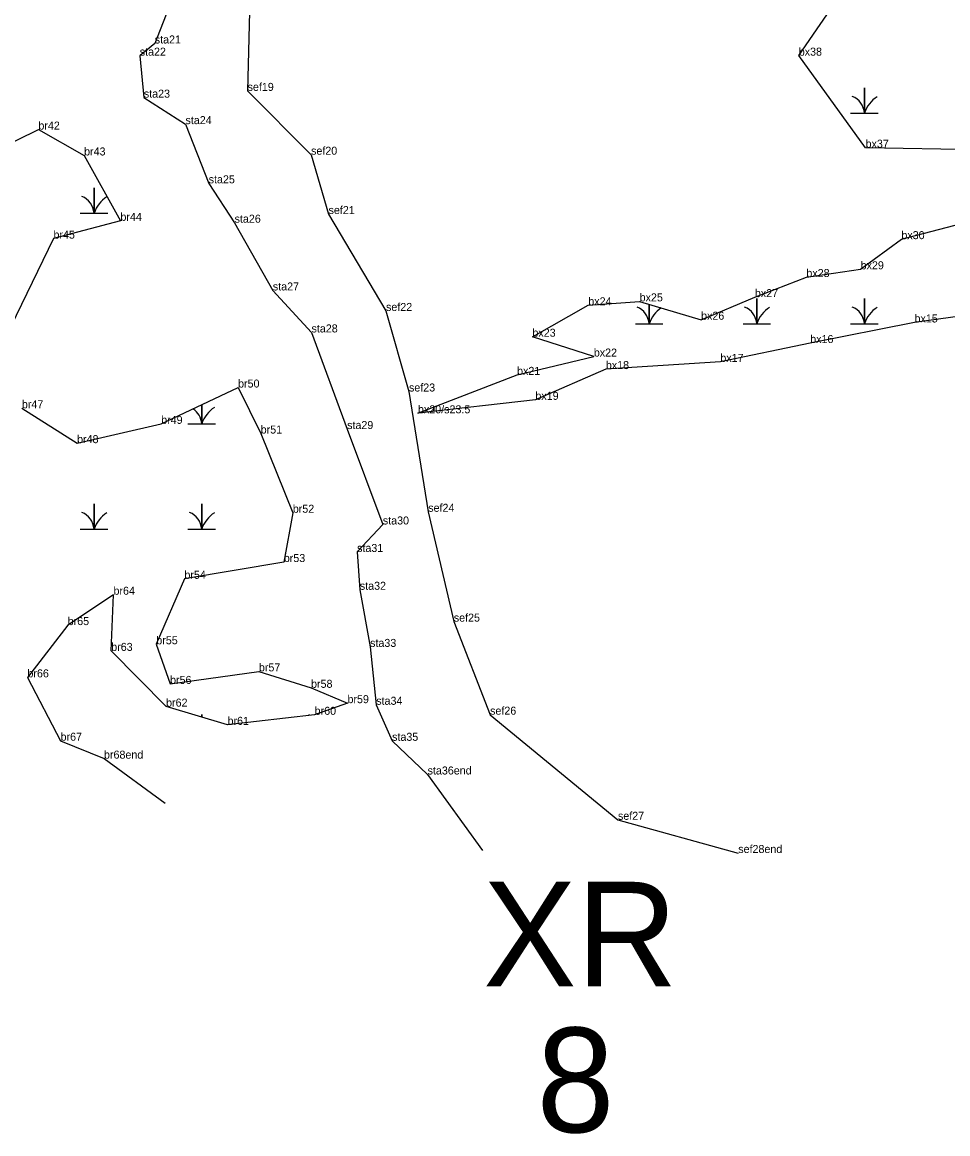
# Model space of a CAD drawing. Extents: x 2072529 to 2268796, y 436423 to 470406.
# Drawn here: x 2233128 to 2233706, y 437609 to 438303 of the extents above; entities that cross this region are included whole.
import ezdxf

# ---------------------------------------------------------------- set-up
doc = ezdxf.new("R2010")
doc.units = 0
for name, color, linetype in [('Default', 7, 'Continuous'), ('Exist Environmental Wetland Boundary Cogo Comment', 7, 'Continuous'), ('Exist Environmental Wetland Boundary Cogo Point CELL', 7, 'Continuous'), ('Exist Hydro Jurisdictional Stream or Body of Water NEU Mitigable Cogo Comment', 7, 'Continuous'), ('Old_Level_20', 7, 'Continuous'), ('Old_Level_52', 7, 'Continuous')]:
    doc.layers.add(name, color=color, linetype=linetype)

msp = doc.modelspace()

# ---------------------------------------------------------------- linework, layer by layer
at = {"layer": 'Exist Environmental Wetland Boundary Cogo Point CELL'}
for points in [[(2233645.48, 438246.13), (2233654.08, 438246.13), (2233654.08, 438261.91), (2233654.08, 438246.13), (2233662.68, 438246.13)], [(2233164.16, 438183.63), (2233172.76, 438183.63), (2233172.76, 438199.41), (2233172.76, 438183.63), (2233181.36, 438183.63)], [(2233510.98, 438114.53), (2233519.58, 438114.53), (2233519.58, 438126.76)], [(2233519.58, 438126.76), (2233519.58, 438114.53), (2233528.18, 438114.53)], [(2233578.23, 438114.53), (2233586.83, 438114.53), (2233586.83, 438130.31), (2233586.83, 438114.53), (2233595.43, 438114.53)], [(2233645.48, 438114.53), (2233654.08, 438114.53), (2233654.08, 438130.31), (2233654.08, 438114.53), (2233662.68, 438114.53)], [(2233231.41, 438052.03), (2233240.01, 438052.03), (2233240.01, 438063.95)], [(2233240.01, 438063.95), (2233240.01, 438052.03), (2233248.61, 438052.03)], [(2233385.08, 438059.74), (2233385.08, 438062.45)], [(2233385.08, 438062.45), (2233385.08, 438059.74)], [(2233164.16, 437986.23), (2233172.76, 437986.23), (2233172.76, 438002.01), (2233172.76, 437986.23), (2233181.36, 437986.23)], [(2233231.41, 437986.23), (2233240.01, 437986.23), (2233240.01, 438002.01), (2233240.01, 437986.23), (2233248.61, 437986.23)], [(2233240.01, 437868.77), (2233240.01, 437870.41), (2233240.01, 437868.77)], [(2233307.26, 437869.86), (2233307.26, 437870.41), (2233307.26, 437869.86)]]:
    msp.add_lwpolyline(points, dxfattribs=at)
for centre, radius, start, end in [((2233641.81, 438245.24), 12.3, 4.14034, 67.53497), ((2233672.32, 438240.07), 19.22, 122.12745, 161.62219), ((2233160.49, 438182.75), 12.3, 4.14034, 67.53497), ((2233191, 438177.57), 19.22, 122.12745, 161.62219), ((2233507.31, 438113.64), 12.3, 4.14034, 67.53497), ((2233537.82, 438108.47), 19.22, 123.57431, 161.62219), ((2233574.56, 438113.64), 12.3, 4.14034, 67.53497), ((2233605.07, 438108.47), 19.22, 122.12745, 161.62219), ((2233641.81, 438113.64), 12.3, 4.14034, 67.53497), ((2233672.32, 438108.47), 19.22, 122.12745, 161.62219), ((2233227.74, 438051.15), 12.3, 4.14034, 56.30829), ((2233258.25, 438045.97), 19.22, 122.12745, 161.62219), ((2233372.81, 438047.84), 12.3, 64.46323, 67.53497), ((2233160.49, 437985.35), 12.3, 4.14034, 67.53497), ((2233191, 437980.17), 19.22, 122.12745, 161.62219), ((2233227.74, 437985.35), 12.3, 4.14034, 67.53497), ((2233258.25, 437980.17), 19.22, 122.12745, 161.62219)]:
    msp.add_arc(centre, radius, start, end, dxfattribs=at)
at = {"layer": 'Old_Level_20'}
for p, q in [((2233210.7, 438289.64), (2233210.7, 438289.64)), ((2233201.3, 438282.01), (2233201.3, 438282.01)), ((2233613.07, 438282.03), (2233613.07, 438282.03)), ((2233268.69, 438260.03), (2233268.69, 438260.03)), ((2233203.87, 438255.8), (2233203.87, 438255.8)), ((2233229.89, 438239.26), (2233229.89, 438239.26)), ((2233137.99, 438235.84), (2233137.99, 438235.84)), ((2233654.83, 438224.52), (2233654.83, 438224.52)), ((2233166.54, 438219.69), (2233166.54, 438219.69)), ((2233308.34, 438220.15), (2233308.34, 438220.15)), ((2233244.38, 438202.27), (2233244.38, 438202.27)), ((2233319.29, 438183.08), (2233319.29, 438183.08)), ((2233189.25, 438178.84), (2233189.25, 438178.84)), ((2233260.58, 438177.67), (2233260.58, 438177.67)), ((2233147.41, 438167.71), (2233147.41, 438167.71)), ((2233677.19, 438167.39), (2233677.19, 438167.39)), ((2233651.73, 438148.58), (2233651.73, 438148.58)), ((2233617.82, 438143.72), (2233617.82, 438143.72)), ((2233284.46, 438135.36), (2233284.46, 438135.36)), ((2233481.56, 438126.08), (2233481.56, 438126.08)), ((2233513.65, 438128.53), (2233513.65, 438128.53)), ((2233585.63, 438131.16), (2233585.63, 438131.16)), ((2233355.17, 438122.55), (2233355.17, 438122.55)), ((2233552.04, 438117.06), (2233552.04, 438117.06)), ((2233685.39, 438115.35), (2233685.39, 438115.35)), ((2233308.64, 438109.12), (2233308.64, 438109.12)), ((2233446.66, 438106.45), (2233446.66, 438106.45)), ((2233620.22, 438102.5), (2233620.22, 438102.5)), ((2233485.02, 438094.05), (2233485.02, 438094.05)), ((2233492.53, 438086.24), (2233492.53, 438086.24)), ((2233564.09, 438090.74), (2233564.09, 438090.74)), ((2233437.07, 438082.61), (2233437.07, 438082.61)), ((2233262.75, 438074.7), (2233262.75, 438074.7)), ((2233369.53, 438072.22), (2233369.53, 438072.22)), ((2233448.52, 438067.02), (2233448.52, 438067.02)), ((2233375.15, 438058.6), (2233375.15, 438058.6)), ((2233214.69, 438051.99), (2233214.69, 438051.99)), ((2233276.88, 438045.98), (2233276.88, 438045.98)), ((2233330.87, 438048.76), (2233330.87, 438048.76)), ((2233162.16, 438039.96), (2233162.16, 438039.96)), ((2233296.94, 437996.49), (2233296.94, 437996.49)), ((2233381.56, 437997.08), (2233381.56, 437997.08)), ((2233353.19, 437989.16), (2233353.19, 437989.16)), ((2233337.09, 437971.98), (2233337.09, 437971.98)), ((2233291.32, 437965.69), (2233291.32, 437965.69)), ((2233229.22, 437955.21), (2233229.22, 437955.21)), ((2233184.9, 437945.25), (2233184.9, 437945.25)), ((2233338.81, 437948.36), (2233338.81, 437948.36)), ((2233156.28, 437926.3), (2233156.28, 437926.3)), ((2233397.53, 437928.46), (2233397.53, 437928.46)), ((2233211.66, 437914.32), (2233211.66, 437914.32)), ((2233345.22, 437912.66), (2233345.22, 437912.66)), ((2233183.48, 437910.18), (2233183.48, 437910.18)), ((2233275.76, 437897.37), (2233275.76, 437897.37)), ((2233131.14, 437893.65), (2233131.14, 437893.65)), ((2233220.26, 437889.55), (2233220.26, 437889.55)), ((2233308.35, 437887.12), (2233308.35, 437887.12)), ((2233331.11, 437877.52), (2233331.11, 437877.52)), ((2233349.07, 437876.52), (2233349.07, 437876.52)), ((2233217.77, 437875.37), (2233217.77, 437875.37)), ((2233310.59, 437870.25), (2233310.59, 437870.25)), ((2233420.19, 437870.33), (2233420.19, 437870.33)), ((2233256.17, 437863.98), (2233256.17, 437863.98)), ((2233151.85, 437854.06), (2233151.85, 437854.06)), ((2233358.97, 437854.01), (2233358.97, 437854.01)), ((2233178.98, 437842.87), (2233178.98, 437842.87)), ((2233381.16, 437832.97), (2233381.16, 437832.97)), ((2233500.1, 437804.66), (2233500.1, 437804.66)), ((2233575.26, 437783.92), (2233575.26, 437783.92))]:
    msp.add_line(p, q, dxfattribs=at)
for points in [[(2233725.42, 438223.22), (2233654.83, 438224.52), (2233613.07, 438282.03), (2233650.73, 438337.13)], [(2233085.81, 438210.21), (2233137.99, 438235.84), (2233166.54, 438219.69), (2233189.25, 438178.84), (2233147.41, 438167.71), (2233113.9, 438099.14)], [(2233736.36, 438122.5), (2233685.39, 438115.35), (2233620.22, 438102.5), (2233564.09, 438090.74), (2233492.53, 438086.24), (2233448.52, 438067.02), (2233375.15, 438058.6), (2233437.07, 438082.61), (2233485.02, 438094.05), (2233446.66, 438106.45), (2233481.56, 438126.08), (2233513.65, 438128.53), (2233552.04, 438117.06), (2233585.63, 438131.16), (2233617.82, 438143.72), (2233651.73, 438148.58), (2233677.19, 438167.39), (2233757.1, 438188.17)], [(2233127.67, 438061.76), (2233162.16, 438039.96), (2233214.69, 438051.99), (2233262.75, 438074.7), (2233276.88, 438045.98), (2233296.94, 437996.49), (2233291.32, 437965.69), (2233229.22, 437955.21), (2233211.66, 437914.32), (2233220.26, 437889.55), (2233275.76, 437897.37), (2233308.35, 437887.12), (2233331.11, 437877.52), (2233310.59, 437870.25), (2233256.17, 437863.98), (2233217.77, 437875.37), (2233183.48, 437910.18), (2233184.9, 437945.25), (2233156.28, 437926.3), (2233131.14, 437893.65), (2233151.85, 437854.06), (2233178.98, 437842.87), (2233217.26, 437814.97)]]:
    msp.add_lwpolyline(points, dxfattribs=at)
at = {"layer": 'Old_Level_52'}
for points in [[(2233270.05, 438317.86), (2233268.69, 438260.03), (2233308.34, 438220.15), (2233319.29, 438183.08), (2233355.17, 438122.55), (2233369.53, 438072.22), (2233381.56, 437997.08), (2233397.53, 437928.46), (2233420.19, 437870.33), (2233500.1, 437804.66), (2233575.26, 437783.92)], [(2233219.22, 438311.43), (2233210.7, 438289.64), (2233201.3, 438282.01), (2233203.87, 438255.8), (2233229.89, 438239.26), (2233244.38, 438202.27), (2233260.58, 438177.67), (2233284.46, 438135.36), (2233308.64, 438109.12), (2233330.87, 438048.76), (2233353.19, 437989.16), (2233337.09, 437971.98), (2233338.81, 437948.36), (2233345.22, 437912.66), (2233349.07, 437876.52), (2233358.97, 437854.01), (2233381.16, 437832.97), (2233415.42, 437785.49)]]:
    msp.add_lwpolyline(points, dxfattribs=at)

# ---------------------------------------------------------------- texts
at = {"layer": 'Default'}
for s, p in [('XR', (2233415.86, 437700.6)), ('8', (2233449.28, 437609.45))]:
    msp.add_text(s, height=65.34, dxfattribs=at).set_placement(p)
at = {"layer": 'Exist Environmental Wetland Boundary Cogo Comment'}
for s, p in [('bx38', (2233613.07, 438282.03)), ('br42', (2233137.99, 438235.84)), ('br43', (2233166.54, 438219.69)), ('bx37', (2233654.83, 438224.52)), ('br44', (2233189.25, 438178.84)), ('br45', (2233147.41, 438167.71)), ('bx30', (2233677.19, 438167.39)), ('bx29', (2233651.73, 438148.58)), ('bx28', (2233617.82, 438143.72)), ('bx25', (2233513.65, 438128.53)), ('bx27', (2233585.63, 438131.16)), ('bx24', (2233481.56, 438126.08)), ('bx26', (2233552.04, 438117.06)), ('bx15', (2233685.39, 438115.35)), ('bx23', (2233446.66, 438106.45)), ('bx16', (2233620.22, 438102.5)), ('bx22', (2233485.02, 438094.05)), ('bx18', (2233492.53, 438086.24)), ('bx17', (2233564.09, 438090.74)), ('br50', (2233262.75, 438074.7)), ('bx19', (2233448.52, 438067.02)), ('br47', (2233127.67, 438061.76)), ('br49', (2233214.69, 438051.99)), ('br51', (2233276.88, 438045.98)), ('br48', (2233162.16, 438039.96)), ('br52', (2233296.94, 437996.49)), ('br53', (2233291.32, 437965.69)), ('br54', (2233229.22, 437955.21)), ('br64', (2233184.9, 437945.25)), ('br65', (2233156.28, 437926.3)), ('br55', (2233211.66, 437914.32)), ('br63', (2233183.48, 437910.18)), ('br66', (2233131.14, 437893.65)), ('br57', (2233275.76, 437897.37)), ('br56', (2233220.26, 437889.55)), ('br58', (2233308.35, 437887.12)), ('br59', (2233331.11, 437877.52)), ('br62', (2233217.77, 437875.37)), ('br61', (2233256.17, 437863.98)), ('br60', (2233310.59, 437870.25)), ('br67', (2233151.85, 437854.06)), ('br68end', (2233178.98, 437842.87))]:
    msp.add_text(s, height=5, dxfattribs=at).set_placement(p)
at = {"layer": 'Exist Hydro Jurisdictional Stream or Body of Water NEU Mitigable Cogo Comment'}
for s, p in [('sta21', (2233210.7, 438289.64)), ('sta22', (2233201.3, 438282.01)), ('sef19', (2233268.69, 438260.03)), ('sta23', (2233203.87, 438255.8)), ('sta24', (2233229.89, 438239.26)), ('sef20', (2233308.34, 438220.15)), ('sta25', (2233244.38, 438202.27)), ('sef21', (2233319.29, 438183.08)), ('sta26', (2233260.58, 438177.67)), ('sta27', (2233284.46, 438135.36)), ('sef22', (2233355.17, 438122.55)), ('sta28', (2233308.64, 438109.12)), ('bx21', (2233437.07, 438082.61)), ('sef23', (2233369.53, 438072.22)), ('bx20/s23.5', (2233375.15, 438058.6)), ('sta29', (2233330.87, 438048.76)), ('sef24', (2233381.56, 437997.08)), ('sta30', (2233353.19, 437989.16)), ('sta31', (2233337.09, 437971.98)), ('sta32', (2233338.81, 437948.36)), ('sef25', (2233397.53, 437928.46)), ('sta33', (2233345.22, 437912.66)), ('sta34', (2233349.07, 437876.52)), ('sef26', (2233420.19, 437870.33)), ('sta35', (2233358.97, 437854.01)), ('sta36end', (2233381.16, 437832.97)), ('sef27', (2233500.1, 437804.66)), ('sef28end', (2233575.26, 437783.92))]:
    msp.add_text(s, height=5, dxfattribs=at).set_placement(p)

doc.saveas('drawing.dxf')
